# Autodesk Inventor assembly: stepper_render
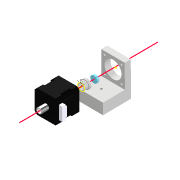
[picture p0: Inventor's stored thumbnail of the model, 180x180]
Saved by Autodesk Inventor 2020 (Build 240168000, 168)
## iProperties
Created: 2022-08
Part Number: stepper_render
Document SubType Name: Assembly
Designer: xmls36
Author: xmls36
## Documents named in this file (6)
- \\homeblue02\xmls36\My_Documents\stepper_render.iam
- C:\Users\xmls36\Downloads\Adapter.ipt
- C:\Users\xmls36\Downloads\SCA4218M1804-L.ipt
- \\homeblue02\xmls36\My_Documents\laser_beam.ipt
- C:\Users\xmls36\Downloads\L-Bracket_chunky.ipt
- \\homeblue02\xmls36\My_Documents\optic.ipt
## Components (5 placed, 5 different names)
1. Adapter:1
2. SCA4218M1804-L:1
3. laser_beam:1
4. L-Bracket_chunky:1
5. optic:1
